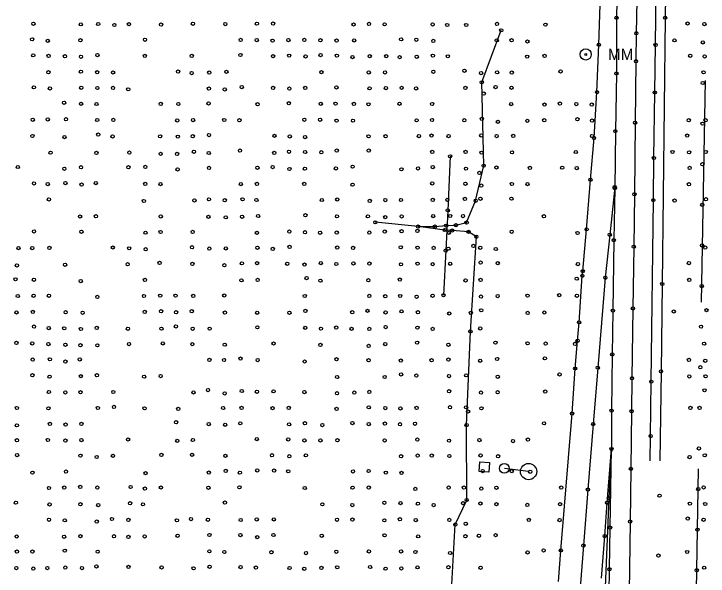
# Model space of a CAD drawing. Extents: x 20503438 to 20508873, y 7964251 to 7984667.
# Drawn here: x 20506272.5 to 20506699.6, y 7972126.6 to 7972472.7 of the extents above; entities that cross this region are included whole.
import ezdxf

# ---------------------------------------------------------------- set-up
doc = ezdxf.new("R2010")
doc.units = 0
for name, color, linetype in [('LTG_Handhole_(prop)', 7, 'Continuous'), ('LTG_Lightpole_(prop)', 7, 'Continuous'), ('SurBreakLine', 7, 'Continuous'), ('SurConcreteSlab', 7, 'Continuous'), ('SurDrainageArrowDown', 7, 'Continuous'), ('SurDrainageArrowUp', 7, 'Continuous'), ('SurEdgeRoadPaved', 7, 'Continuous'), ('SurEdgeShoulderPaved', 7, 'Continuous'), ('SurFenceWire', 7, 'Continuous'), ('SurPointsNonDTM', 7, 'Continuous'), ('SurRoadPoints', 7, 'Continuous'), ('SurSurveyPoints', 7, 'Continuous')]:
    doc.layers.add(name, color=color, linetype=linetype)

msp = doc.modelspace()

# ---------------------------------------------------------------- linework, layer by layer
at = {"layer": 'LTG_Handhole_(prop)'}
msp.add_lwpolyline([(20506558.64, 7972190.98), (20506559.11, 7972196.96), (20506565.09, 7972196.49), (20506564.62, 7972190.51)], close=True, dxfattribs=at)
at = {"layer": 'LTG_Lightpole_(prop)'}
msp.add_line((20506589.09, 7972190.96), (20506574.22, 7972192.94), dxfattribs=at)
for centre, radius in [((20506574.22, 7972192.94), 3), ((20506574.22, 7972192.94), 3), ((20506589.09, 7972190.96), 5), ((20506589.09, 7972190.96), 5)]:
    msp.add_circle(centre, radius, dxfattribs=at)
at = {"layer": 'SurBreakLine'}
msp.add_lwpolyline([(20506655.64, 7972480.95), (20506655.39, 7972460.82), (20506655.17, 7972443.54), (20506654.63, 7972405.71), (20506654.2, 7972361.71), (20506653.83, 7972329.4), (20506653.32, 7972291.37), (20506652.72, 7972248.45), (20506652.47, 7972228.07), (20506652.04, 7972192.65), (20506651.55, 7972160.21), (20506650.91, 7972116.84)], dxfattribs=at)
at = {"layer": 'SurConcreteSlab'}
msp.add_lwpolyline([(20506642.14, 7972366.07), (20506639.08, 7972336.72), (20506636.31, 7972310.27), (20506631.66, 7972254.92), (20506628.84, 7972220.16), (20506625.58, 7972179.88), (20506622.82, 7972145.41), (20506619.83, 7972106.64), (20506617.55, 7972077.44), (20506614.39, 7972037.44), (20506611.55, 7972002.25), (20506608.47, 7971964.14), (20506606.82, 7971943.7), (20506604.21, 7971911.77), (20506601.07, 7971874.33), (20506597.29, 7971820.97), (20506592.84, 7971766.38), (20506586.66, 7971713.81), (20506582.25, 7971691.18)], dxfattribs=at)
at = {"layer": 'SurDrainageArrowDown'}
msp.add_line((20506695.47, 7972295.28), (20506697.87, 7972431.67), dxfattribs=at)
for points in [[(20506527.98, 7971858.82), (20506531.51, 7971910.07), (20506533.31, 7971971.31), (20506537.16, 7972033.43), (20506540.68, 7972099.35), (20506544.03, 7972158.32), (20506551.03, 7972173.45), (20506550.99, 7972219.57), (20506553.33, 7972277.23), (20506556.97, 7972335.48), (20506552.21, 7972338.55), (20506542.12, 7972339.37), (20506537.65, 7972339.65), (20506521.13, 7972341.81), (20506494.82, 7972344.4)], [(20506692.15, 7972105.21), (20506693.01, 7972155.2), (20506693.45, 7972180.19), (20506693.67, 7972192.56)]]:
    msp.add_lwpolyline(points, dxfattribs=at)
at = {"layer": 'SurDrainageArrowUp'}
msp.add_lwpolyline([(20506521.13, 7972341.81), (20506531.5, 7972341.78), (20506538.47, 7972342.35), (20506544.39, 7972342.64), (20506550.97, 7972344.26), (20506556.55, 7972357.69), (20506561.5, 7972379.29), (20506560.29, 7972430.59), (20506572.32, 7972462.6)], dxfattribs=at)
at = {"layer": 'SurEdgeRoadPaved'}
for points in [[(20506663.98, 7972197.66), (20506664.2, 7972212.79), (20506664.61, 7972246.33), (20506665.88, 7972358.05), (20506666.2, 7972384.01), (20506666.76, 7972424.32), (20506667.23, 7972453.6), (20506667.84, 7972505.25), (20506669.4, 7972614.97), (20506671.57, 7972775.78), (20506671.83, 7972814.97), (20506672.54, 7972877.32), (20506673.22, 7972920.01), (20506674.66, 7973031.32)], [(20506607.55, 7972123.27), (20506608.96, 7972142.44), (20506615.91, 7972226.68), (20506617.78, 7972254.42), (20506619.22, 7972271.47), (20506620.18, 7972282.83), (20506622.16, 7972311.47), (20506622.42, 7972314.33), (20506624.83, 7972340.08), (20506627.19, 7972370.59), (20506629.38, 7972396.4), (20506631.18, 7972424.53), (20506632.33, 7972453.69), (20506633.86, 7972497.27)], [(20506643.62, 7972491.27), (20506643.19, 7972470.31), (20506643.14, 7972436.02), (20506642.49, 7972400.52), (20506642.13, 7972365.44), (20506641.49, 7972333.42), (20506640.97, 7972290.02), (20506640.58, 7972263.1), (20506640.19, 7972228.47), (20506640.12, 7972204.86)], [(20506631.19, 7971502.09), (20506632.45, 7971595.12), (20506632.85, 7971632.62), (20506633.14, 7971655.73), (20506634.01, 7971711.21), (20506635.31, 7971820.02), (20506635.83, 7971898.92), (20506636.44, 7971934.73), (20506636.57, 7971964.61), (20506636.93, 7972009.35), (20506637.82, 7972058.1), (20506638.22, 7972086.53), (20506638.83, 7972130.85), (20506639.25, 7972156.46), (20506640.12, 7972204.86)]]:
    msp.add_lwpolyline(points, dxfattribs=at)
at = {"layer": 'SurEdgeShoulderPaved'}
for points in [[(20506681.39, 7973102.17), (20506680.61, 7973023.61), (20506678.88, 7972898.17), (20506677.96, 7972835.87), (20506677.24, 7972770.07), (20506676.37, 7972707.06), (20506676.17, 7972692.84), (20506676.07, 7972684.34), (20506675.16, 7972614.83), (20506674.88, 7972581.01), (20506673.14, 7972470.38), (20506671.33, 7972306.45), (20506670.58, 7972252.62), (20506669.95, 7972197.58)], [(20506633.96, 7972125.3), (20506635.93, 7972151.22), (20506637.43, 7972171.74), (20506640.12, 7972204.86), (20506638.55, 7972174.56), (20506635.97, 7972114.83)]]:
    msp.add_lwpolyline(points, dxfattribs=at)
at = {"layer": 'SurFenceWire'}
msp.add_lwpolyline([(20506540.81, 7972385.04), (20506539.42, 7972351.78), (20506538.12, 7972327.02), (20506536.76, 7972299.5)], dxfattribs=at)
at = {"layer": 'SurPointsNonDTM'}
for centre in [(20506561.57, 7972423.66), (20506540.81, 7972385.04), (20506558.86, 7972374.82), (20506539.42, 7972351.78), (20506538.12, 7972327.02), (20506555.21, 7972329.88), (20506536.76, 7972299.5), (20506553.59, 7972288.61), (20506551.88, 7972227.93), (20506550.44, 7972158.8)]:
    msp.add_circle(centre, 1, dxfattribs=at)
at = {"layer": 'SurRoadPoints'}
for radius in [3.43, 0.571]:
    msp.add_circle((20506624.27, 7972447.74), radius, dxfattribs=at)
at = {"layer": 'SurSurveyPoints'}
for centre in [(20506643.19, 7972470.31), (20506673.14, 7972470.38), (20506284.5, 7972466.67), (20506313.66, 7972466.27), (20506324.36, 7972466.49), (20506334.29, 7972465.88), (20506343.22, 7972466.38), (20506363.03, 7972466.14), (20506382.58, 7972466.67), (20506402.55, 7972466.41), (20506421.98, 7972466.68), (20506431.96, 7972466.77), (20506481.43, 7972466.18), (20506490.92, 7972466.55), (20506500.55, 7972466.28), (20506530.09, 7972466.25), (20506539.04, 7972465.88), (20506550.79, 7972465.89), (20506569.67, 7972466.58), (20506572.32, 7972462.6), (20506599.45, 7972466.09), (20506686.95, 7972466.8), (20506697.32, 7972466.42), (20506655.39, 7972460.82), (20506283.67, 7972457.06), (20506293.31, 7972456.13), (20506313.42, 7972456.49), (20506353.11, 7972456.78), (20506411.97, 7972456.73), (20506421.89, 7972456.56), (20506431.63, 7972456.25), (20506441.36, 7972456.6), (20506451.17, 7972456.67), (20506461.08, 7972456.5), (20506471.01, 7972456.32), (20506481.81, 7972456.41), (20506510.71, 7972457.04), (20506520.04, 7972456.78), (20506530.51, 7972456.1), (20506569.51, 7972456.43), (20506578.66, 7972456.51), (20506588.43, 7972455.71), (20506678.89, 7972456.43), (20506696.32, 7972455.15), (20506632.33, 7972453.69), (20506667.23, 7972453.6), (20506284.4, 7972447.19), (20506293.81, 7972446.83), (20506303.85, 7972446.63), (20506313.74, 7972446.33), (20506323.84, 7972447.36), (20506353.02, 7972446.83), (20506381.93, 7972446.88), (20506411.83, 7972447.42), (20506431.91, 7972446.7), (20506441.83, 7972447), (20506451.9, 7972446.56), (20506461.16, 7972447.32), (20506471.17, 7972447.01), (20506480.79, 7972446.11), (20506491.39, 7972446.68), (20506501.55, 7972446.7), (20506509.8, 7972446.08), (20506520.35, 7972446.31), (20506530.28, 7972447), (20506539.43, 7972446.59), (20506588.25, 7972446.39), (20506598.96, 7972446.88), (20506688.58, 7972446.93), (20506697.43, 7972446.56), (20506655.17, 7972443.54), (20506313.67, 7972437.13), (20506373.52, 7972437.2), (20506403.21, 7972437.05), (20506530.53, 7972437.11), (20506549.62, 7972437.68), (20506608.8, 7972437.31), (20506293.74, 7972436.82), (20506323.7, 7972436.81), (20506333.53, 7972436.63), (20506381.84, 7972436.27), (20506392.67, 7972436.59), (20506461.64, 7972436.85), (20506490.82, 7972436.66), (20506500.8, 7972436.69), (20506559.89, 7972436.3), (20506569.74, 7972436.73), (20506578.75, 7972436.58), (20506643.14, 7972436.02), (20506696.77, 7972436.74), (20506560.29, 7972430.59), (20506696.22, 7972430.15), (20506284.77, 7972427.48), (20506294.64, 7972426.8), (20506313.92, 7972427.26), (20506323.82, 7972427.07), (20506333.46, 7972427.13), (20506342.84, 7972426.28), (20506392.45, 7972426.76), (20506402.22, 7972426.24), (20506412.66, 7972427.62), (20506431.95, 7972427.15), (20506441.95, 7972426.75), (20506451.68, 7972427.12), (20506470.89, 7972427.44), (20506491.31, 7972426.88), (20506501.32, 7972427.04), (20506511.02, 7972427.19), (20506519.91, 7972426.8), (20506550.25, 7972427.17), (20506568.8, 7972427.62), (20506578.61, 7972427.21), (20506631.18, 7972424.53), (20506666.76, 7972424.32), (20506303.36, 7972418), (20506313.82, 7972417.35), (20506323.29, 7972417.24), (20506362.83, 7972417.29), (20506373.65, 7972417.23), (20506392.24, 7972417.59), (20506422.38, 7972417.07), (20506441.62, 7972417.68), (20506461.27, 7972417.35), (20506470.37, 7972417.47), (20506481.68, 7972417.27), (20506490.62, 7972417.04), (20506509.69, 7972417.39), (20506529.73, 7972417.25), (20506578.39, 7972417.21), (20506598.9, 7972416.86), (20506608.4, 7972417.48), (20506618.47, 7972417.2), (20506628, 7972416.89), (20506284.07, 7972407.55), (20506293.33, 7972407.75), (20506304.53, 7972407.83), (20506323.75, 7972407.39), (20506333.66, 7972407.46), (20506372.98, 7972407.11), (20506382.71, 7972407.33), (20506401.86, 7972407.41), (20506411.24, 7972407.24), (20506451.17, 7972407.52), (20506460.82, 7972407.52), (20506520.26, 7972407.17), (20506529.7, 7972407.41), (20506549.57, 7972407.27), (20506560.35, 7972408.08), (20506598.75, 7972407.24), (20506619.18, 7972407.87), (20506628.21, 7972407.04), (20506687.64, 7972407.23), (20506697.98, 7972407.27), (20506470.98, 7972407), (20506481.07, 7972406.98), (20506570.24, 7972406.26), (20506588.34, 7972406.89), (20506654.63, 7972405.71), (20506696.13, 7972405.15), (20506642.49, 7972400.52), (20506283.88, 7972397.56), (20506303.61, 7972396.9), (20506324.38, 7972398.4), (20506333.17, 7972397.27), (20506362.41, 7972397.35), (20506373.34, 7972397.15), (20506382.52, 7972397.39), (20506392.5, 7972398.09), (20506432.81, 7972397.64), (20506442.2, 7972397.25), (20506451.65, 7972396.87), (20506490.69, 7972397.34), (20506501.13, 7972397.37), (20506521.61, 7972397.47), (20506529.39, 7972397.83), (20506539.91, 7972397.5), (20506559.99, 7972397.87), (20506569.47, 7972397.5), (20506579.65, 7972397.57), (20506628.12, 7972397.54), (20506629.38, 7972396.4), (20506686.68, 7972397.82), (20506295.03, 7972387.28), (20506323.24, 7972387.13), (20506343.51, 7972387.33), (20506362.76, 7972386.57), (20506372.88, 7972386.52), (20506383.23, 7972387.81), (20506392.33, 7972387.07), (20506411.57, 7972388.57), (20506432.64, 7972387.13), (20506441.72, 7972387.82), (20506451.62, 7972387.69), (20506461.59, 7972387.53), (20506471.11, 7972388.54), (20506490.82, 7972388.59), (20506529.84, 7972387.77), (20506550.32, 7972387.74), (20506560.15, 7972387.3), (20506578.93, 7972387.49), (20506618.18, 7972387.67), (20506677.65, 7972387.7), (20506687.85, 7972387.49), (20506698.14, 7972387.7), (20506666.2, 7972384.01), (20506274.91, 7972378.45), (20506303.53, 7972377.4), (20506313.78, 7972378.34), (20506342.93, 7972378.31), (20506353.36, 7972378.51), (20506392.51, 7972377.9), (20506422.29, 7972378.01), (20506431.66, 7972378.38), (20506441.97, 7972377.25), (20506451.51, 7972377.41), (20506470.58, 7972377.57), (20506480.88, 7972378.64), (20506521.09, 7972377.55), (20506530.18, 7972378.41), (20506550.59, 7972377.45), (20506561.5, 7972379.29), (20506569.3, 7972378.14), (20506589.91, 7972377.91), (20506609.82, 7972378.04), (20506618.73, 7972377.81), (20506688.2, 7972377.87), (20506696.03, 7972380.15), (20506373.19, 7972376.97), (20506510.88, 7972377.04), (20506627.19, 7972370.59), (20506284.83, 7972368.37), (20506293.32, 7972367.94), (20506304.15, 7972368.55), (20506314.08, 7972367.66), (20506322.88, 7972368.54), (20506353.29, 7972368.05), (20506362.66, 7972367.93), (20506412.08, 7972367.93), (20506421.99, 7972368.08), (20506451.08, 7972368.07), (20506480.85, 7972367.57), (20506529.83, 7972368.34), (20506550.29, 7972368.17), (20506559.97, 7972367.05), (20506578.82, 7972368.01), (20506588.44, 7972367.92), (20506642.13, 7972365.44), (20506642.14, 7972366.07), (20506687.74, 7972367.87), (20506654.2, 7972361.71), (20506294.04, 7972358.51), (20506352.46, 7972357.53), (20506383.55, 7972357.87), (20506392.48, 7972358.54), (20506402.18, 7972357.98), (20506413.14, 7972358.56), (20506421.67, 7972358.14), (20506461.91, 7972358.12), (20506471.41, 7972358.45), (20506491.4, 7972357.6), (20506500.97, 7972358.08), (20506510.62, 7972358.14), (20506530.14, 7972358.22), (20506539.11, 7972358.24), (20506549.94, 7972358.84), (20506556.55, 7972357.69), (20506559.52, 7972358.91), (20506578.57, 7972358.94), (20506665.88, 7972358.05), (20506678.91, 7972357.77), (20506698.25, 7972358.59), (20506695.94, 7972355.16), (20506313.18, 7972347.98), (20506322.93, 7972348.13), (20506362.83, 7972348.02), (20506392.13, 7972347.78), (20506402.81, 7972347.47), (20506412.87, 7972347.84), (20506422.74, 7972348.28), (20506451.83, 7972348.76), (20506471.23, 7972348.07), (20506490.28, 7972348.07), (20506500.95, 7972347.58), (20506511.02, 7972348.03), (20506530.41, 7972348.24), (20506540.88, 7972348.31), (20506548.78, 7972348.21), (20506598.53, 7972348.13), (20506494.82, 7972344.4), (20506550.97, 7972344.26), (20506284.85, 7972338.78), (20506441.95, 7972338.72), (20506511, 7972338.93), (20506520.74, 7972339.11), (20506521.13, 7972341.81), (20506531.5, 7972341.78), (20506537.65, 7972339.65), (20506538.47, 7972342.35), (20506542.12, 7972339.37), (20506544.39, 7972342.64), (20506624.83, 7972340.08), (20506314.03, 7972338.6), (20506353.43, 7972338.01), (20506362.74, 7972338.45), (20506382.45, 7972338.51), (20506421.97, 7972337.93), (20506451.57, 7972338.3), (20506460.83, 7972337.98), (20506471.1, 7972338.12), (20506491.12, 7972338.06), (20506500.61, 7972338.69), (20506540.05, 7972337.92), (20506552.21, 7972338.55), (20506556.97, 7972335.48), (20506578.73, 7972338.61), (20506619.25, 7972337.83), (20506639.08, 7972336.72), (20506641.49, 7972333.42), (20506275.3, 7972328.54), (20506283.76, 7972328.55), (20506294.36, 7972328.62), (20506333.34, 7972328.91), (20506343.4, 7972328.4), (20506353.55, 7972327.8), (20506382.06, 7972329.09), (20506392.71, 7972328.22), (20506402.86, 7972328.3), (20506422.28, 7972328.74), (20506431.76, 7972328.06), (20506442.06, 7972329.26), (20506471.42, 7972328.89), (20506481.18, 7972328.62), (20506510.45, 7972329.03), (20506520.83, 7972328.81), (20506530.7, 7972328.63), (20506539.79, 7972328.17), (20506559.35, 7972328.71), (20506568.91, 7972327.97), (20506653.83, 7972329.4), (20506695.84, 7972330.16), (20506697.81, 7972328.89), (20506274.34, 7972317.85), (20506303.99, 7972318.3), (20506342.46, 7972318.6), (20506362.11, 7972319.41), (20506382.33, 7972318.82), (20506401.95, 7972317.96), (20506412.75, 7972319.13), (20506422.11, 7972319.25), (20506440.61, 7972318.88), (20506451.25, 7972318.39), (20506461.3, 7972319.29), (20506470.83, 7972318.72), (20506481.35, 7972319.11), (20506491.22, 7972319.04), (20506510.61, 7972318.56), (20506520.79, 7972318.97), (20506530.11, 7972318.65), (20506540.86, 7972318.86), (20506559.61, 7972319.64), (20506570.17, 7972319.25), (20506619.44, 7972318.68), (20506687.73, 7972319.27), (20506622.42, 7972314.33), (20506273.47, 7972309.32), (20506284.77, 7972309.05), (20506353.1, 7972308.95), (20506422.44, 7972308.96), (20506452.5, 7972310.06), (20506509.91, 7972309.17), (20506559.55, 7972308.97), (20506618.78, 7972309.69), (20506622.16, 7972311.47), (20506636.31, 7972310.27), (20506687.97, 7972308.94), (20506313.62, 7972308.23), (20506412.43, 7972308.68), (20506461.07, 7972308.48), (20506490.55, 7972308.72), (20506550.36, 7972308.65), (20506671.33, 7972306.45), (20506695.64, 7972305.16), (20506274.83, 7972299.04), (20506284.6, 7972299.18), (20506294.03, 7972299.16), (20506323.82, 7972298.49), (20506352.51, 7972299.06), (20506362.48, 7972299.26), (20506371.96, 7972299.27), (20506382.83, 7972299.13), (20506401.85, 7972299.36), (20506451.43, 7972299.06), (20506491.12, 7972299.11), (20506500.93, 7972298.88), (20506510.12, 7972299.05), (20506520.26, 7972298.57), (20506530.02, 7972299.2), (20506559.84, 7972298.72), (20506570.11, 7972298.97), (20506588.5, 7972299.25), (20506607.98, 7972299.56), (20506618.82, 7972299.21), (20506274.07, 7972288.95), (20506284.13, 7972289.27), (20506304.32, 7972289.02), (20506314.78, 7972288.73), (20506353.01, 7972289.25), (20506363.05, 7972289.65), (20506372.24, 7972289.08), (20506381.87, 7972289.69), (20506402.3, 7972288.87), (20506422.13, 7972288.7), (20506441.99, 7972288.71), (20506451.85, 7972289.84), (20506480.62, 7972289.07), (20506490.01, 7972289.92), (20506501.12, 7972288.92), (20506510.92, 7972289.58), (20506521, 7972289.04), (20506540.31, 7972288.26), (20506560, 7972290.24), (20506588.56, 7972288.64), (20506598.79, 7972288.89), (20506640.97, 7972290.02), (20506653.32, 7972291.37), (20506678.44, 7972289.51), (20506698.56, 7972290.32), (20506284.85, 7972280.2), (20506293.96, 7972279.28), (20506303.47, 7972279.14), (20506323.46, 7972279.4), (20506372.12, 7972280.3), (20506392.91, 7972278.95), (20506422.24, 7972279.76), (20506451.68, 7972279.45), (20506461.39, 7972278.95), (20506470.77, 7972279.62), (20506501.18, 7972279.89), (20506520.76, 7972279.56), (20506559.38, 7972279.08), (20506620.18, 7972282.83), (20506695.2, 7972280.17), (20506313.71, 7972278.74), (20506342.59, 7972278.89), (20506363.26, 7972278.91), (20506382.48, 7972278.9), (20506480.19, 7972278.84), (20506491.12, 7972278.82), (20506530.09, 7972278.81), (20506553.33, 7972277.23), (20506619.22, 7972271.47), (20506274.02, 7972270.17), (20506283.73, 7972269.82), (20506293.71, 7972269.46), (20506304.16, 7972269.04), (20506313.41, 7972268.72), (20506323.83, 7972268.69), (20506343.29, 7972269.43), (20506364.11, 7972269.85), (20506382.25, 7972269.39), (20506402.23, 7972269.07), (20506432.25, 7972269.8), (20506461.04, 7972268.97), (20506490.71, 7972268.32), (20506500.93, 7972269.45), (20506520.53, 7972270.34), (20506539.81, 7972269.05), (20506568.69, 7972270.32), (20506588.51, 7972269.92), (20506599.62, 7972269.78), (20506617.67, 7972269.55), (20506697.07, 7972269.68), (20506640.58, 7972263.1), (20506284.03, 7972259.91), (20506294.66, 7972260.06), (20506304.17, 7972258.71), (20506313.02, 7972259.97), (20506392.8, 7972259.73), (20506401.75, 7972259.67), (20506411.88, 7972260.53), (20506422.46, 7972259.61), (20506451.34, 7972258.73), (20506470.95, 7972260.1), (20506490.7, 7972259.52), (20506510.52, 7972259.29), (20506529.46, 7972259.48), (20506539.8, 7972259.93), (20506559.32, 7972259.19), (20506569.74, 7972260.27), (20506599.14, 7972260.67), (20506687.72, 7972259.71), (20506697.81, 7972259.15), (20506617.78, 7972254.42), (20506631.66, 7972254.92), (20506694.76, 7972255.17), (20506283.9, 7972250.27), (20506294.4, 7972249.37), (20506313.66, 7972249.69), (20506323.53, 7972250.28), (20506352.56, 7972249.36), (20506362.76, 7972249.73), (20506471.33, 7972249.16), (20506500.59, 7972249.2), (20506510.71, 7972250.75), (20506520.08, 7972250.04), (20506540.15, 7972249.72), (20506550.77, 7972250.2), (20506570.18, 7972249.34), (20506608.17, 7972250.74), (20506670.58, 7972252.62), (20506688, 7972249.51), (20506697.98, 7972249.6), (20506652.72, 7972248.45), (20506664.61, 7972246.33), (20506391.91, 7972241.1), (20506412.64, 7972240.54), (20506697.34, 7972240.98), (20506294.04, 7972239.92), (20506304.13, 7972239.71), (20506313.46, 7972239.81), (20506333.63, 7972239.97), (20506382.97, 7972239.66), (20506402.15, 7972239.07), (20506421.98, 7972240.09), (20506432.21, 7972240.34), (20506451.24, 7972239.89), (20506471.27, 7972239.18), (20506481.89, 7972239.62), (20506491.13, 7972239.98), (20506540.18, 7972240.43), (20506559.86, 7972239.6), (20506570.07, 7972239.83), (20506599.38, 7972240.22), (20506274.36, 7972230.1), (20506293.69, 7972229.91), (20506324.15, 7972230.11), (20506334.04, 7972230.78), (20506352.9, 7972229.91), (20506373.55, 7972229.54), (20506401.19, 7972230.09), (20506412.56, 7972230.13), (20506431.59, 7972229.99), (20506441.58, 7972230.13), (20506470.97, 7972229.56), (20506490.77, 7972230.49), (20506500.98, 7972230.06), (20506510.3, 7972229.8), (20506520.17, 7972230.18), (20506540.77, 7972230.56), (20506550.65, 7972230.5), (20506560.13, 7972229.91), (20506640.19, 7972228.47), (20506652.47, 7972228.07), (20506688.65, 7972230.13), (20506694.33, 7972230.18), (20506615.91, 7972226.68), (20506274.31, 7972219.42), (20506294.63, 7972220.3), (20506304.29, 7972219.91), (20506314.03, 7972220.31), (20506372.26, 7972221.34), (20506392.37, 7972220.2), (20506402.46, 7972219.8), (20506411.78, 7972220.63), (20506441.8, 7972220.03), (20506451.52, 7972220.73), (20506462.24, 7972219.56), (20506480.73, 7972220.78), (20506490.8, 7972220.21), (20506500.74, 7972220.51), (20506510.03, 7972220.09), (20506519.25, 7972220.37), (20506550.99, 7972219.57), (20506598.61, 7972220.65), (20506628.84, 7972220.16), (20506342.73, 7972210.7), (20506421.94, 7972210.95), (20506441.24, 7972210.73), (20506520.68, 7972210.68), (20506588.7, 7972210.63), (20506664.2, 7972212.79), (20506274.32, 7972210.26), (20506293.38, 7972210.42), (20506304.18, 7972210.02), (20506314.04, 7972210.35), (20506372.96, 7972209.89), (20506382.57, 7972210.38), (20506451.22, 7972210.13), (20506461.04, 7972210.16), (20506471.54, 7972210.28), (20506500.55, 7972210.15), (20506540.16, 7972209.99), (20506558.84, 7972210.36), (20506579.52, 7972209.69), (20506640.12, 7972204.86), (20506640.12, 7972204.86), (20506640.12, 7972204.86), (20506693.89, 7972205.18), (20506274.45, 7972201.08), (20506313.38, 7972200.76), (20506323.41, 7972199.95), (20506333.37, 7972200.64), (20506363.21, 7972201.2), (20506382.11, 7972201.27), (20506402.62, 7972200.64), (20506431.25, 7972201.04), (20506441.92, 7972200.41), (20506452.14, 7972200.94), (20506510.65, 7972200.4), (20506520.86, 7972200.83), (20506529.57, 7972200.84), (20506540.37, 7972200.54), (20506559.6, 7972200.87), (20506570.34, 7972200.38), (20506688.16, 7972199.86), (20506697.48, 7972200.97), (20506283.88, 7972190.29), (20506304.51, 7972190.96), (20506353.47, 7972189.98), (20506392.41, 7972190.36), (20506402.8, 7972191.37), (20506411.55, 7972190.28), (20506422.17, 7972191.67), (20506432.57, 7972191.58), (20506441.27, 7972191.12), (20506481.1, 7972191.06), (20506490.73, 7972191.3), (20506501.29, 7972190.31), (20506510.93, 7972190.12), (20506560.86, 7972191.23), (20506578.76, 7972191.2), (20506590.11, 7972190.81), (20506652.04, 7972192.65), (20506294.06, 7972180.86), (20506303.45, 7972181.08), (20506313.3, 7972181.52), (20506323.81, 7972181.09), (20506344.31, 7972181.46), (20506362.91, 7972181.15), (20506392.17, 7972181.01), (20506411.24, 7972181.26), (20506451.45, 7972180.84), (20506480.85, 7972181.04), (20506490.77, 7972181.13), (20506539.93, 7972181.12), (20506549.33, 7972181.14), (20506569.36, 7972180.96), (20506609.21, 7972181.1), (20506696.81, 7972181.17), (20506353.1, 7972180.52), (20506519.43, 7972180.32), (20506560.03, 7972180.5), (20506625.58, 7972179.88), (20506693.45, 7972180.19), (20506551.03, 7972173.45), (20506638.55, 7972174.56), (20506669.71, 7972176.11), (20506273.73, 7972171.8), (20506294.42, 7972170.76), (20506313.38, 7972170.83), (20506324.36, 7972170.32), (20506343.93, 7972171.48), (20506351.88, 7972170.79), (20506402.26, 7972171.87), (20506462.24, 7972170.81), (20506480.66, 7972170.35), (20506500.38, 7972171.75), (20506510.32, 7972171.55), (20506521.02, 7972171.18), (20506530.71, 7972170.31), (20506548.82, 7972171.52), (20506559.47, 7972171.31), (20506569.35, 7972170.89), (20506588.34, 7972170.46), (20506608.5, 7972170.89), (20506637.43, 7972171.74), (20506688.33, 7972171.21), (20506697.8, 7972171.01), (20506294.05, 7972161.3), (20506303.76, 7972160.92), (20506323.46, 7972160.17), (20506332.83, 7972161.78), (20506342.95, 7972161.18), (20506372.73, 7972160.96), (20506381.43, 7972161.73), (20506391.81, 7972161.32), (20506411.99, 7972161.14), (20506421.89, 7972161.52), (20506432.4, 7972161.53), (20506471.26, 7972161.31), (20506480.74, 7972161.43), (20506500.37, 7972160.96), (20506509.97, 7972161.6), (20506519.69, 7972161.06), (20506540.36, 7972161.23), (20506589.27, 7972161.22), (20506608.16, 7972161.09), (20506651.55, 7972160.21), (20506687.02, 7972162.01), (20506696.76, 7972161.31), (20506544.03, 7972158.32), (20506639.25, 7972156.46), (20506693.01, 7972155.2), (20506274.19, 7972150.99), (20506303.33, 7972150.83), (20506313.44, 7972151.2), (20506334.06, 7972151.18), (20506352.91, 7972151), (20506373.17, 7972151.42), (20506392.74, 7972151.92), (20506411.87, 7972151.83), (20506432.16, 7972151.91), (20506461.86, 7972151.45), (20506500.53, 7972151.72), (20506521.19, 7972151.09), (20506550.29, 7972151.18), (20506558.55, 7972151.46), (20506568.85, 7972151.82), (20506635.93, 7972151.22), (20506342.94, 7972150.77), (20506422.19, 7972150.58), (20506303.8, 7972142.29), (20506598.37, 7972142.4), (20506608.96, 7972142.44), (20506622.82, 7972145.41), (20506274.3, 7972141.68), (20506283.87, 7972141.7), (20506324.03, 7972141.63), (20506392.73, 7972141.85), (20506401.94, 7972141.43), (20506430.94, 7972141.3), (20506452.2, 7972140.79), (20506470.82, 7972141.6), (20506490.89, 7972141.78), (20506510.66, 7972141.77), (20506519.53, 7972141.46), (20506540.8, 7972140.82), (20506588.51, 7972141.16), (20506668.97, 7972139.22), (20506686.68, 7972141.45), (20506273.98, 7972131.55), (20506284.41, 7972131.22), (20506293.06, 7972131.51), (20506304.12, 7972131.88), (20506314.36, 7972131.54), (20506323.25, 7972132.56), (20506342.98, 7972132.28), (20506363.31, 7972131.93), (20506383.04, 7972131.4), (20506392.83, 7972132.33), (20506411.92, 7972132.13), (20506421.37, 7972131.89), (20506442.06, 7972131.59), (20506451.12, 7972131.15), (20506461.69, 7972131.66), (20506471.37, 7972132.02), (20506491.59, 7972132.21), (20506501.1, 7972131.18), (20506510.83, 7972131.34), (20506520.78, 7972132), (20506539.8, 7972132.08), (20506559.56, 7972131.72), (20506638.83, 7972130.85), (20506692.58, 7972130.2), (20506697.14, 7972131.79)]:
    msp.add_circle(centre, 1, dxfattribs=at)

# ---------------------------------------------------------------- texts
at = {"layer": 'SurRoadPoints'}
msp.add_text('MM', height=6.995, rotation=360, dxfattribs=at).set_placement((20506637.98, 7972444.24))

doc.saveas('drawing.dxf')
